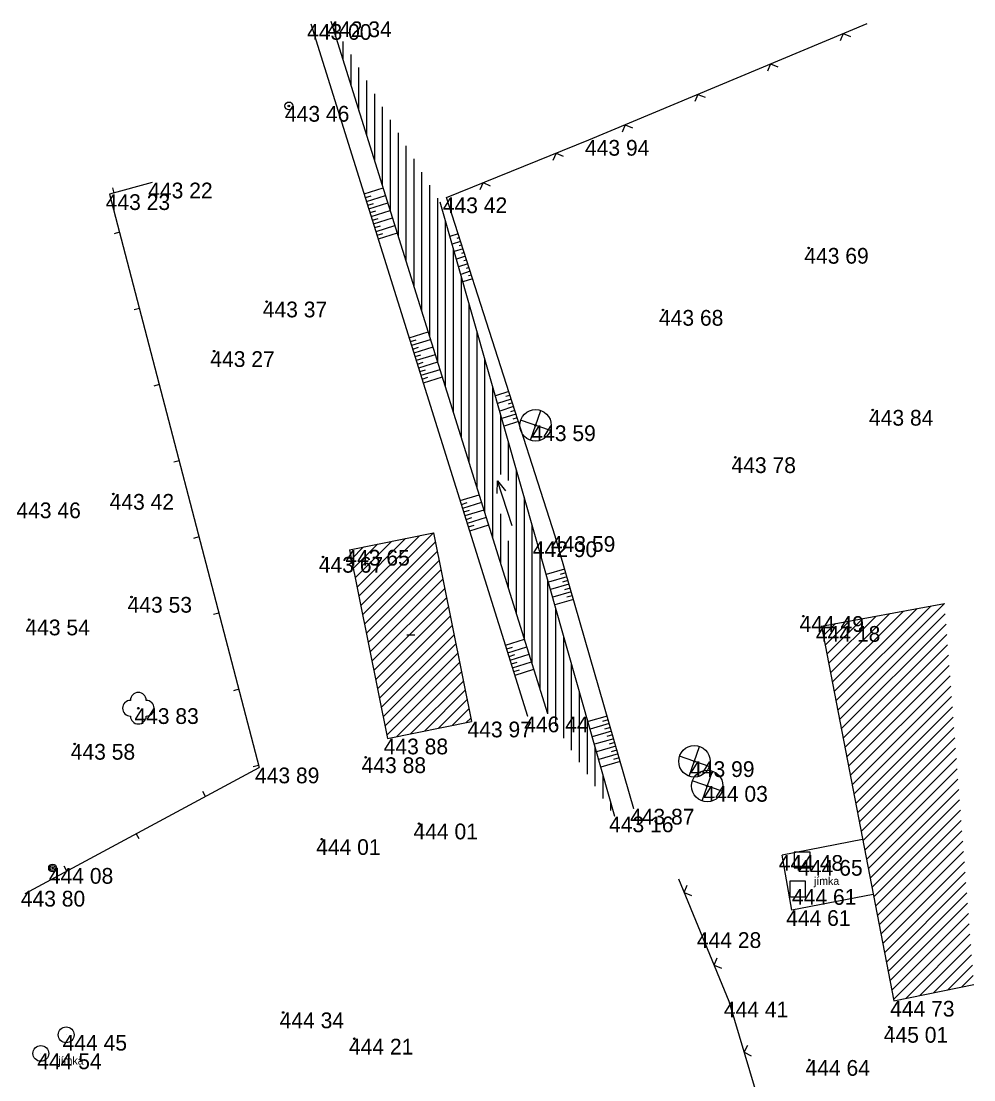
# Model space of a CAD drawing. Extents: x -554123 to -553118, y -1076825 to -1073672.
# Drawn here: x -553923.9 to -553863.5, y -1074659.7 to -1074592.4 of the extents above; entities that cross this region are included whole.
import ezdxf

# ---------------------------------------------------------------- set-up
doc = ezdxf.new("R2010")
doc.units = 0
for name, color, linetype in [('1', 7, 'Continuous'), ('12', 7, 'Continuous'), ('14', 7, 'Continuous'), ('18', 7, 'Continuous'), ('20', 7, 'Continuous'), ('26', 7, 'Continuous'), ('27', 7, 'Continuous'), ('28', 7, 'Continuous'), ('32', 7, 'Continuous'), ('33', 7, 'Continuous'), ('34', 7, 'Continuous'), ('40', 7, 'Continuous'), ('47', 7, 'Continuous'), ('50', 7, 'Continuous'), ('52', 7, 'Continuous'), ('6', 7, 'Continuous')]:
    doc.layers.add(name, color=color, linetype=linetype)

# ---------------------------------------------------------------- blocks, each defined once
blk = doc.blocks.new('POINT_DISPLAY')
blk.add_line((0, 0), (0, 0))
blk = doc.blocks.new('SA')
at = {"layer": '50'}
blk.add_lwpolyline([(-0.5, -0.5), (0.5, -0.5), (0.5, 0.5), (-0.5, 0.5)], close=True, dxfattribs=at)
blk = doc.blocks.new('STJ')
at = {"layer": '34'}
for p, q in [((-0.327, -0.945), (0.327, 0.945)), ((0.945, -0.327), (-0.945, 0.327))]:
    blk.add_line(p, q, dxfattribs=at)
for radius in [1, 0.0496]:
    blk.add_circle((0, 0), radius, dxfattribs=at)
blk = doc.blocks.new('T')
at = {"layer": '6'}
blk.add_circle((0, 0), 0.05, dxfattribs=at)
blk = doc.blocks.new('ME')
at = {"layer": '33'}
for radius in [0.25, 0.05]:
    blk.add_circle((0, 0), radius, dxfattribs=at)
blk = doc.blocks.new('STL')
at = {"layer": '34'}
blk.add_circle((0, 0), 0.05, dxfattribs=at)
for centre, start, end in [((0, 0.5), 0, 180), ((-0.5, 0), 90, 270), ((0.5, 0), 270, 90), ((0, -0.5), 180, 0)]:
    blk.add_arc(centre, 0.5, start, end, dxfattribs=at)
blk = doc.blocks.new('SLDP')
at = {"layer": '20'}
for radius in [0.25, 0.158, 0.05]:
    blk.add_circle((0, 0), radius, dxfattribs=at)
blk = doc.blocks.new('BN')
at = {"layer": '47'}
blk.add_line((-0.25, 0), (0.25, 0), dxfattribs=at)
blk = doc.blocks.new('VOTOK')
at = {"layer": '28'}
for p, q in [((-3.001, 0), (0, 0)), ((-0.75, 0.282), (0, 0)), ((0, 0), (-0.75, -0.28))]:
    blk.add_line(p, q, dxfattribs=at)
blk = doc.blocks.new('SAK')
at = {"layer": '40'}
blk.add_circle((0, 0), 0.5, dxfattribs=at)

msp = doc.modelspace()

# ---------------------------------------------------------------- linework, layer by layer
at = {"layer": '12'}
for p, q in [((-553887.9, -1074599.96), (-553870.23, -1074592.56)), ((-553871.758, -1074593.2), (-553871.948, -1074593.663)), ((-553871.758, -1074593.2), (-553871.295, -1074593.39)), ((-553876.37, -1074595.131), (-553876.56, -1074595.595)), ((-553876.37, -1074595.131), (-553875.907, -1074595.321)), ((-553880.982, -1074597.063), (-553881.172, -1074597.526)), ((-553880.982, -1074597.063), (-553880.519, -1074597.253)), ((-553885.594, -1074598.994), (-553885.784, -1074599.458)), ((-553885.594, -1074598.994), (-553885.131, -1074599.184)), ((-553896.94, -1074603.61), (-553887.9, -1074599.96)), ((-553889.985, -1074600.802), (-553890.181, -1074601.263)), ((-553889.985, -1074600.802), (-553889.525, -1074600.998)), ((-553915.63, -1074602.67), (-553918.33, -1074603.41)), ((-553894.622, -1074602.674), (-553894.818, -1074603.135)), ((-553894.622, -1074602.674), (-553894.161, -1074602.87)), ((-553918.33, -1074603.41), (-553908.84, -1074639.83)), ((-553918.041, -1074603.331), (-553918.134, -1074602.993)), ((-553917.7, -1074605.829), (-553918.038, -1074605.917)), ((-553916.439, -1074610.668), (-553916.778, -1074610.756)), ((-553915.178, -1074615.506), (-553915.517, -1074615.594)), ((-553913.917, -1074620.345), (-553914.256, -1074620.433)), ((-553912.657, -1074625.183), (-553912.995, -1074625.271)), ((-553911.396, -1074630.021), (-553911.735, -1074630.11)), ((-553910.135, -1074634.86), (-553910.474, -1074634.948)), ((-553923.695, -1074647.83), (-553908.84, -1074639.83)), ((-553908.874, -1074639.698), (-553909.213, -1074639.787)), ((-553912.249, -1074641.666), (-553912.415, -1074641.358)), ((-553916.651, -1074644.037), (-553916.486, -1074644.345)), ((-553921.054, -1074646.408), (-553921.22, -1074646.099)), ((-553879, -1074654.7), (-553882.195, -1074646.914)), ((-553881.847, -1074647.761), (-553881.654, -1074647.3)), ((-553881.847, -1074647.761), (-553881.385, -1074647.955)), ((-553879.949, -1074652.387), (-553879.756, -1074651.925)), ((-553879.949, -1074652.387), (-553879.487, -1074652.58)), ((-553877.32, -1074660.3), (-553879, -1074654.7)), ((-553878.038, -1074657.905), (-553877.801, -1074657.465)), ((-553878.038, -1074657.905), (-553877.598, -1074658.143))]:
    msp.add_line(p, q, dxfattribs=at)
at = {"layer": '14'}
for p, q in [((-553903.1, -1074626), (-553897.77, -1074624.92)), ((-553897.77, -1074624.92), (-553895.35, -1074636.91)), ((-553903.1, -1074626), (-553900.68, -1074637.99)), ((-553873.14, -1074630.84), (-553865.329, -1074629.416)), ((-553873.14, -1074630.84), (-553868.54, -1074654.65)), ((-553900.68, -1074637.99), (-553895.35, -1074636.91)), ((-553868.54, -1074654.65), (-553863.462, -1074653.608))]:
    msp.add_line(p, q, dxfattribs=at)
at = {"layer": '18'}
for p, q in [((-553870.519, -1074644.405), (-553875.62, -1074645.39)), ((-553875.02, -1074648.89), (-553875.62, -1074645.39)), ((-553869.846, -1074647.89), (-553875.02, -1074648.89))]:
    msp.add_line(p, q, dxfattribs=at)
at = {"layer": '26'}
for p, q in [((-553902.164, -1074603.385), (-553900.959, -1074603.008)), ((-553902.089, -1074603.624), (-553901.728, -1074603.511)), ((-553902.015, -1074603.862), (-553900.81, -1074603.485)), ((-553901.94, -1074604.101), (-553901.578, -1074603.988)), ((-553901.865, -1074604.339), (-553900.66, -1074603.962)), ((-553901.791, -1074604.578), (-553901.429, -1074604.465)), ((-553901.716, -1074604.816), (-553900.511, -1074604.439)), ((-553901.567, -1074605.294), (-553900.361, -1074604.917)), ((-553901.641, -1074605.055), (-553901.28, -1074604.942)), ((-553901.492, -1074605.532), (-553901.13, -1074605.419)), ((-553901.417, -1074605.771), (-553900.212, -1074605.394)), ((-553901.343, -1074606.009), (-553900.981, -1074605.896)), ((-553901.268, -1074606.248), (-553900.063, -1074605.871)), ((-553896.199, -1074605.925), (-553896.721, -1074606.092)), ((-553896.123, -1074606.163), (-553896.281, -1074606.214)), ((-553896.046, -1074606.401), (-553896.584, -1074606.573)), ((-553895.894, -1074606.877), (-553896.447, -1074607.054)), ((-553895.97, -1074606.639), (-553896.134, -1074606.692)), ((-553895.741, -1074607.353), (-553896.31, -1074607.535)), ((-553895.818, -1074607.115), (-553895.986, -1074607.169)), ((-553895.665, -1074607.592), (-553895.838, -1074607.647)), ((-553895.589, -1074607.83), (-553896.172, -1074608.017)), ((-553895.513, -1074608.068), (-553895.69, -1074608.125)), ((-553895.437, -1074608.306), (-553896.035, -1074608.498)), ((-553895.284, -1074608.782), (-553895.898, -1074608.979)), ((-553895.36, -1074608.544), (-553895.542, -1074608.602)), ((-553899.302, -1074612.527), (-553898.097, -1074612.15)), ((-553899.228, -1074612.766), (-553898.866, -1074612.653)), ((-553899.153, -1074613.004), (-553897.948, -1074612.627)), ((-553899.078, -1074613.243), (-553898.717, -1074613.13)), ((-553899.004, -1074613.481), (-553897.799, -1074613.104)), ((-553898.929, -1074613.72), (-553898.567, -1074613.607)), ((-553898.854, -1074613.959), (-553897.649, -1074613.582)), ((-553898.78, -1074614.197), (-553898.418, -1074614.084)), ((-553898.705, -1074614.436), (-553897.5, -1074614.059)), ((-553898.63, -1074614.674), (-553898.269, -1074614.561)), ((-553898.555, -1074614.913), (-553897.35, -1074614.536)), ((-553898.406, -1074615.39), (-553897.201, -1074615.013)), ((-553898.481, -1074615.151), (-553898.119, -1074615.038)), ((-553892.99, -1074615.948), (-553893.834, -1074616.218)), ((-553892.913, -1074616.186), (-553893.169, -1074616.268)), ((-553892.837, -1074616.424), (-553893.697, -1074616.699)), ((-553892.685, -1074616.901), (-553893.56, -1074617.181)), ((-553892.761, -1074616.662), (-553893.021, -1074616.746)), ((-553892.532, -1074617.377), (-553893.423, -1074617.662)), ((-553892.609, -1074617.139), (-553892.873, -1074617.224)), ((-553892.456, -1074617.615), (-553892.725, -1074617.701)), ((-553892.38, -1074617.853), (-553893.286, -1074618.143)), ((-553896.064, -1074622.873), (-553894.859, -1074622.496)), ((-553895.989, -1074623.112), (-553895.627, -1074622.999)), ((-553895.914, -1074623.351), (-553894.709, -1074622.974)), ((-553895.84, -1074623.589), (-553895.478, -1074623.476)), ((-553895.765, -1074623.828), (-553894.56, -1074623.451)), ((-553895.69, -1074624.066), (-553895.329, -1074623.953)), ((-553895.616, -1074624.305), (-553894.41, -1074623.928)), ((-553895.541, -1074624.543), (-553895.179, -1074624.43)), ((-553895.466, -1074624.782), (-553894.261, -1074624.405)), ((-553889.443, -1074627.23), (-553890.604, -1074627.566)), ((-553889.304, -1074627.71), (-553890.467, -1074628.047)), ((-553889.373, -1074627.47), (-553889.722, -1074627.571)), ((-553889.165, -1074628.19), (-553890.331, -1074628.527)), ((-553889.234, -1074627.95), (-553889.584, -1074628.051)), ((-553889.095, -1074628.431), (-553889.446, -1074628.532)), ((-553889.026, -1074628.671), (-553890.195, -1074629.009)), ((-553888.956, -1074628.911), (-553889.308, -1074629.013)), ((-553888.887, -1074629.151), (-553890.059, -1074629.49)), ((-553893.19, -1074632.054), (-553891.985, -1074631.677)), ((-553893.115, -1074632.293), (-553892.754, -1074632.18)), ((-553893.04, -1074632.532), (-553891.835, -1074632.155)), ((-553892.966, -1074632.77), (-553892.604, -1074632.657)), ((-553892.891, -1074633.009), (-553891.686, -1074632.632)), ((-553892.816, -1074633.247), (-553892.455, -1074633.134)), ((-553892.742, -1074633.486), (-553891.536, -1074633.109)), ((-553892.667, -1074633.725), (-553892.305, -1074633.612)), ((-553892.592, -1074633.963), (-553891.387, -1074633.586)), ((-553886.744, -1074636.56), (-553887.957, -1074636.911)), ((-553886.605, -1074637.04), (-553887.821, -1074637.392)), ((-553886.674, -1074636.8), (-553887.039, -1074636.906)), ((-553886.466, -1074637.521), (-553887.685, -1074637.874)), ((-553886.535, -1074637.281), (-553886.901, -1074637.386)), ((-553886.396, -1074637.761), (-553886.763, -1074637.867)), ((-553886.327, -1074638.001), (-553887.549, -1074638.354)), ((-553886.188, -1074638.481), (-553887.412, -1074638.835)), ((-553886.257, -1074638.241), (-553886.624, -1074638.347)), ((-553886.049, -1074638.962), (-553887.276, -1074639.317)), ((-553886.118, -1074638.722), (-553886.486, -1074638.828)), ((-553885.98, -1074639.202), (-553886.348, -1074639.308)), ((-553885.91, -1074639.442), (-553887.14, -1074639.798))]:
    msp.add_line(p, q, dxfattribs=at)
at = {"layer": '27'}
for p, q in [((-553891.77, -1074636.59), (-553905.54, -1074592.6)), ((-553890.05, -1074625.13), (-553896.94, -1074603.61)), ((-553885.04, -1074642.45), (-553890.05, -1074625.13))]:
    msp.add_line(p, q, dxfattribs=at)
at = {"layer": '28'}
for p, q in [((-553890.5, -1074636.42), (-553904.27, -1074592.43)), ((-553891.2, -1074625.46), (-553897.34, -1074603.92)), ((-553886.25, -1074642.94), (-553891.2, -1074625.46))]:
    msp.add_line(p, q, dxfattribs=at)
at = {"layer": '32'}
for p, q in [((-553904, -1074593.293), (-553904, -1074592.878)), ((-553903.5, -1074594.89), (-553903.5, -1074593.707)), ((-553903, -1074596.487), (-553903, -1074594.536)), ((-553902.5, -1074598.084), (-553902.5, -1074595.365)), ((-553902, -1074599.682), (-553902, -1074596.194)), ((-553901.5, -1074601.279), (-553901.5, -1074597.023)), ((-553901, -1074602.876), (-553901, -1074597.852)), ((-553900.5, -1074604.474), (-553900.5, -1074598.681)), ((-553900, -1074606.071), (-553900, -1074599.51)), ((-553899.5, -1074607.668), (-553899.5, -1074600.339)), ((-553899, -1074609.266), (-553899, -1074601.168)), ((-553898.5, -1074610.863), (-553898.5, -1074601.997)), ((-553898, -1074612.46), (-553898, -1074602.826)), ((-553897.5, -1074614.058), (-553897.5, -1074603.655)), ((-553897, -1074615.655), (-553897, -1074605.113)), ((-553896.5, -1074617.252), (-553896.5, -1074606.867)), ((-553896, -1074618.85), (-553896, -1074608.621)), ((-553895.5, -1074620.447), (-553895.5, -1074610.375)), ((-553895, -1074622.044), (-553895, -1074612.129)), ((-553894.5, -1074623.641), (-553894.5, -1074613.883)), ((-553894, -1074625.239), (-553894, -1074615.637)), ((-553893.5, -1074621.223), (-553893.5, -1074617.391)), ((-553893, -1074621.593), (-553893, -1074619.145)), ((-553892.5, -1074630.031), (-553892.5, -1074620.899)), ((-553892, -1074631.628), (-553892, -1074622.653)), ((-553893.5, -1074626.836), (-553893.5, -1074623.712)), ((-553891.5, -1074633.225), (-553891.5, -1074624.408)), ((-553902.505, -1074628.948), (-553898.657, -1074625.1)), ((-553902.386, -1074629.536), (-553897.77, -1074624.92)), ((-553902.861, -1074627.183), (-553901.317, -1074625.639)), ((-553902.743, -1074627.771), (-553900.43, -1074625.459)), ((-553902.624, -1074628.36), (-553899.544, -1074625.279)), ((-553902.268, -1074630.125), (-553897.651, -1074625.508)), ((-553893, -1074628.433), (-553893, -1074625.436)), ((-553903.099, -1074626.006), (-553903.091, -1074625.998)), ((-553902.98, -1074626.594), (-553902.204, -1074625.818)), ((-553902.149, -1074630.713), (-553897.532, -1074626.097)), ((-553891, -1074634.823), (-553891, -1074626.166)), ((-553902.03, -1074631.301), (-553897.414, -1074626.685)), ((-553901.911, -1074631.89), (-553897.295, -1074627.273)), ((-553901.793, -1074632.478), (-553897.176, -1074627.862)), ((-553901.674, -1074633.066), (-553897.057, -1074628.45)), ((-553890.5, -1074636.42), (-553890.5, -1074627.932)), ((-553901.555, -1074633.655), (-553896.939, -1074629.038)), ((-553901.436, -1074634.243), (-553896.82, -1074629.627)), ((-553890, -1074637.187), (-553890, -1074629.698)), ((-553872.335, -1074635.008), (-553867.059, -1074629.731)), ((-553872.22, -1074635.6), (-553866.194, -1074629.574)), ((-553872.106, -1074636.193), (-553865.329, -1074629.416)), ((-553901.318, -1074634.831), (-553896.701, -1074630.215)), ((-553872.793, -1074632.637), (-553870.518, -1074630.362)), ((-553872.678, -1074633.23), (-553869.653, -1074630.204)), ((-553872.564, -1074633.822), (-553868.788, -1074630.047)), ((-553872.449, -1074634.415), (-553867.923, -1074629.889)), ((-553871.991, -1074636.785), (-553865.278, -1074630.072)), ((-553901.199, -1074635.42), (-553896.582, -1074630.804)), ((-553873.136, -1074630.859), (-553873.112, -1074630.835)), ((-553873.022, -1074631.452), (-553872.247, -1074630.677)), ((-553872.907, -1074632.045), (-553871.382, -1074630.52)), ((-553871.877, -1074637.378), (-553865.228, -1074630.729)), ((-553901.08, -1074636.008), (-553896.464, -1074631.392)), ((-553889.5, -1074637.954), (-553889.5, -1074631.463)), ((-553871.762, -1074637.971), (-553865.177, -1074631.385)), ((-553900.961, -1074636.597), (-553896.345, -1074631.98)), ((-553871.648, -1074638.563), (-553865.126, -1074632.042)), ((-553900.842, -1074637.185), (-553896.226, -1074632.569)), ((-553900.724, -1074637.773), (-553896.107, -1074633.157)), ((-553871.533, -1074639.156), (-553865.076, -1074632.698)), ((-553900.12, -1074637.877), (-553895.989, -1074633.745)), ((-553889, -1074638.721), (-553889, -1074633.229)), ((-553871.419, -1074639.749), (-553865.025, -1074633.355)), ((-553899.233, -1074637.697), (-553895.87, -1074634.334)), ((-553871.304, -1074640.341), (-553864.974, -1074634.011)), ((-553898.346, -1074637.517), (-553895.751, -1074634.922)), ((-553888.5, -1074639.488), (-553888.5, -1074634.995)), ((-553871.19, -1074640.934), (-553864.924, -1074634.668)), ((-553897.46, -1074637.337), (-553895.632, -1074635.51)), ((-553871.075, -1074641.526), (-553864.873, -1074635.324)), ((-553896.573, -1074637.158), (-553895.514, -1074636.099)), ((-553870.961, -1074642.119), (-553864.822, -1074635.98)), ((-553895.686, -1074636.978), (-553895.395, -1074636.687)), ((-553888, -1074640.255), (-553888, -1074636.76)), ((-553870.846, -1074642.712), (-553864.772, -1074636.637)), ((-553870.732, -1074643.304), (-553864.721, -1074637.293)), ((-553887.5, -1074641.022), (-553887.5, -1074638.526)), ((-553870.617, -1074643.897), (-553864.67, -1074637.95)), ((-553870.503, -1074644.489), (-553864.62, -1074638.606)), ((-553870.388, -1074645.082), (-553864.569, -1074639.263)), ((-553887, -1074641.789), (-553887, -1074640.292)), ((-553870.274, -1074645.675), (-553864.518, -1074639.919)), ((-553870.16, -1074646.267), (-553864.468, -1074640.576)), ((-553870.045, -1074646.86), (-553864.417, -1074641.232)), ((-553869.931, -1074647.453), (-553864.366, -1074641.888)), ((-553886.5, -1074642.556), (-553886.5, -1074642.057)), ((-553869.816, -1074648.045), (-553864.316, -1074642.545)), ((-553869.702, -1074648.638), (-553864.265, -1074643.201)), ((-553869.587, -1074649.23), (-553864.214, -1074643.858)), ((-553869.473, -1074649.823), (-553864.164, -1074644.514)), ((-553869.358, -1074650.416), (-553864.113, -1074645.171)), ((-553869.244, -1074651.008), (-553864.062, -1074645.827)), ((-553869.129, -1074651.601), (-553864.012, -1074646.484)), ((-553869.015, -1074652.193), (-553863.961, -1074647.14)), ((-553868.9, -1074652.786), (-553863.91, -1074647.796)), ((-553868.786, -1074653.379), (-553863.86, -1074648.453)), ((-553868.671, -1074653.971), (-553863.809, -1074649.109)), ((-553868.557, -1074654.564), (-553863.759, -1074649.766)), ((-553867.78, -1074654.494), (-553863.708, -1074650.422)), ((-553866.89, -1074654.311), (-553863.657, -1074651.079)), ((-553866, -1074654.129), (-553863.607, -1074651.735)), ((-553865.111, -1074653.946), (-553863.556, -1074652.392)), ((-553864.221, -1074653.764), (-553863.505, -1074653.048))]:
    msp.add_line(p, q, dxfattribs=at)

# ---------------------------------------------------------------- block references
at = {"layer": '1'}
for p in [(-553905.54, -1074592.6), (-553904.27, -1074592.43), (-553906.95, -1074597.8), (-553887.9, -1074599.96), (-553915.63, -1074602.67), (-553918.33, -1074603.41), (-553897.34, -1074603.92), (-553896.94, -1074603.61), (-553873.95, -1074606.82), (-553908.36, -1074610.23), (-553883.19, -1074610.76), (-553911.69, -1074613.38), (-553869.88, -1074617.11), (-553891.29, -1074618.09), (-553891.29, -1074618.09), (-553878.6, -1074620.12), (-553918.09, -1074622.45), (-553891.2, -1074625.46), (-553890.05, -1074625.13), (-553904.79, -1074626.45), (-553903.1, -1074626), (-553916.94, -1074628.99), (-553923.44, -1074630.43), (-553874.29, -1074630.21), (-553873.14, -1074630.84), (-553916.51, -1074636.06), (-553895.35, -1074636.91), (-553891.77, -1074636.59), (-553920.55, -1074638.33), (-553900.68, -1074637.99), (-553902.08, -1074639.18), (-553908.84, -1074639.83), (-553881.2, -1074639.43), (-553880.39, -1074641), (-553885.04, -1074642.45), (-553886.25, -1074642.94), (-553898.69, -1074643.39), (-553904.87, -1074644.38), (-553875.62, -1074645.39), (-553874.36, -1074645.7), (-553921.95, -1074646.21), (-553923.72, -1074647.66), (-553874.65, -1074647.55), (-553875.02, -1074648.89), (-553880.81, -1074650.29), (-553879, -1074654.7), (-553868.54, -1074654.65), (-553907.31, -1074655.39), (-553868.82, -1074656.31), (-553921.09, -1074656.81), (-553902.79, -1074657.06), (-553922.7, -1074657.99), (-553873.91, -1074658.41)]:
    msp.add_blockref('POINT_DISPLAY', p, dxfattribs=at)
at = {"layer": '20'}
msp.add_blockref('SLDP', (-553921.95, -1074646.21), dxfattribs=at)
at = {"layer": '26'}
msp.add_blockref('POINT_DISPLAY', (-553870.32, -1074592.6), dxfattribs=at)
at = {"layer": '28', "xscale": 1.0000012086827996, "yscale": 1.0000012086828, "rotation": 107.94702567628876}
msp.add_blockref('VOTOK', (-553893.697, -1074621.623), dxfattribs=at)
at = {"layer": '32'}
for p in [(-553897.77, -1074624.92), (-553865.329, -1074629.416)]:
    msp.add_blockref('POINT_DISPLAY', p, dxfattribs=at)
at = {"layer": '33'}
msp.add_blockref('ME', (-553906.95, -1074597.8), dxfattribs=at)
at = {"layer": '34'}
for name, p in [('STJ', (-553891.29, -1074618.09)), ('STJ', (-553891.29, -1074618.09)), ('STL', (-553916.51, -1074636.06)), ('STJ', (-553881.2, -1074639.43)), ('STJ', (-553880.39, -1074641))]:
    msp.add_blockref(name, p, dxfattribs=at)
at = {"layer": '40'}
for p in [(-553921.09, -1074656.81), (-553922.7, -1074657.99)]:
    msp.add_blockref('SAK', p, dxfattribs=at)
at = {"layer": '47'}
msp.add_blockref('BN', (-553899.206, -1074631.409), dxfattribs=at)
at = {"layer": '50'}
for p in [(-553874.36, -1074645.7), (-553874.65, -1074647.55)]:
    msp.add_blockref('SA', p, dxfattribs=at)
at = {"layer": '6'}
for p in [(-553873.95, -1074606.82), (-553908.36, -1074610.23), (-553883.19, -1074610.76), (-553911.69, -1074613.38), (-553869.88, -1074617.11), (-553878.6, -1074620.12), (-553918.09, -1074622.45), (-553904.79, -1074626.45), (-553916.94, -1074628.99), (-553923.44, -1074630.43), (-553874.29, -1074630.21), (-553920.55, -1074638.33), (-553902.08, -1074639.18), (-553898.69, -1074643.39), (-553904.87, -1074644.38), (-553907.31, -1074655.39), (-553868.82, -1074656.31), (-553902.79, -1074657.06), (-553873.91, -1074658.41)]:
    msp.add_blockref('T', p, dxfattribs=at)

# ---------------------------------------------------------------- texts
at = {"layer": '52'}
for p in [(-553873.606, -1074647.283), (-553921.582, -1074658.696)]:
    msp.add_text('jímka', height=0.5, dxfattribs=at).set_placement(p)
at = {"layer": '6'}
for s, p in [('443 00 ', (-553905.794, -1074593.6)), ('442 34 ', (-553904.508, -1074593.43)), ('443 46 ', (-553907.2, -1074598.8)), ('443 94 ', (-553888.15, -1074600.96)), ('443 22 ', (-553915.88, -1074603.67)), ('443 23 ', (-553918.58, -1074604.41)), ('443 42 ', (-553897.178, -1074604.61)), ('443 69 ', (-553874.224, -1074607.82)), ('443 37 ', (-553908.608, -1074611.23)), ('443 68 ', (-553883.452, -1074611.76)), ('443 27 ', (-553911.938, -1074614.38)), ('443 84 ', (-553870.118, -1074618.11)), ('443 59 ', (-553891.552, -1074619.09)), ('443 59 ', (-553891.552, -1074619.09)), ('443 78 ', (-553878.848, -1074621.12)), ('443 46 ', (-553924.25, -1074623.99)), ('443 42 ', (-553918.328, -1074623.45)), ('442 90 ', (-553891.464, -1074626.46)), ('443 59 ', (-553890.312, -1074626.13)), ('443 67 ', (-553905.05, -1074627.45)), ('443 65 ', (-553903.362, -1074627)), ('443 53 ', (-553917.19, -1074629.99)), ('443 54 ', (-553923.678, -1074631.43)), ('444 49 ', (-553874.528, -1074631.21)), ('444 18 ', (-553873.487, -1074631.84)), ('443 83 ', (-553916.76, -1074637.06)), ('443 97 ', (-553895.61, -1074637.91)), ('446 44 ', (-553892.008, -1074637.59)), ('443 58 ', (-553920.8, -1074639.33)), ('443 88 ', (-553900.93, -1074638.99)), ('443 88 ', (-553902.33, -1074640.18)), ('443 89 ', (-553909.102, -1074640.83)), ('443 99 ', (-553881.474, -1074640.43)), ('444 03 ', (-553880.63, -1074642)), ('443 87 ', (-553885.288, -1074643.45)), ('443 16 ', (-553886.621, -1074643.94)), ('444 01 ', (-553899.037, -1074644.39)), ('444 01 ', (-553905.217, -1074645.38)), ('444 48 ', (-553875.846, -1074646.39)), ('444 65 ', (-553874.61, -1074646.7)), ('444 08 ', (-553922.19, -1074647.21)), ('443 80 ', (-553923.972, -1074648.66)), ('444 61 ', (-553875.007, -1074648.55)), ('444 61 ', (-553875.377, -1074649.89)), ('444 28 ', (-553881.048, -1074651.29)), ('444 41 ', (-553879.333, -1074655.7)), ('444 73 ', (-553868.776, -1074655.65)), ('444 34 ', (-553907.536, -1074656.39)), ('445 01 ', (-553869.179, -1074657.31)), ('444 45 ', (-553921.316, -1074657.81)), ('444 21 ', (-553903.135, -1074658.06)), ('444 54 ', (-553922.926, -1074658.99)), ('444 64 ', (-553874.148, -1074659.41))]:
    msp.add_text(s, height=1, dxfattribs=at).set_placement(p)

doc.saveas('drawing.dxf')
